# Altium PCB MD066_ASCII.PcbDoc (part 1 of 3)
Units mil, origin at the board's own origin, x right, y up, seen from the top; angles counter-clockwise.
Board outline 4255 x 2850 mil, 4 copper layers (Top Layer, Ground, Power, Bottom Layer), stack 61.6 mil thick; 158 components, 78 nets, 405 pads, 639 vias.
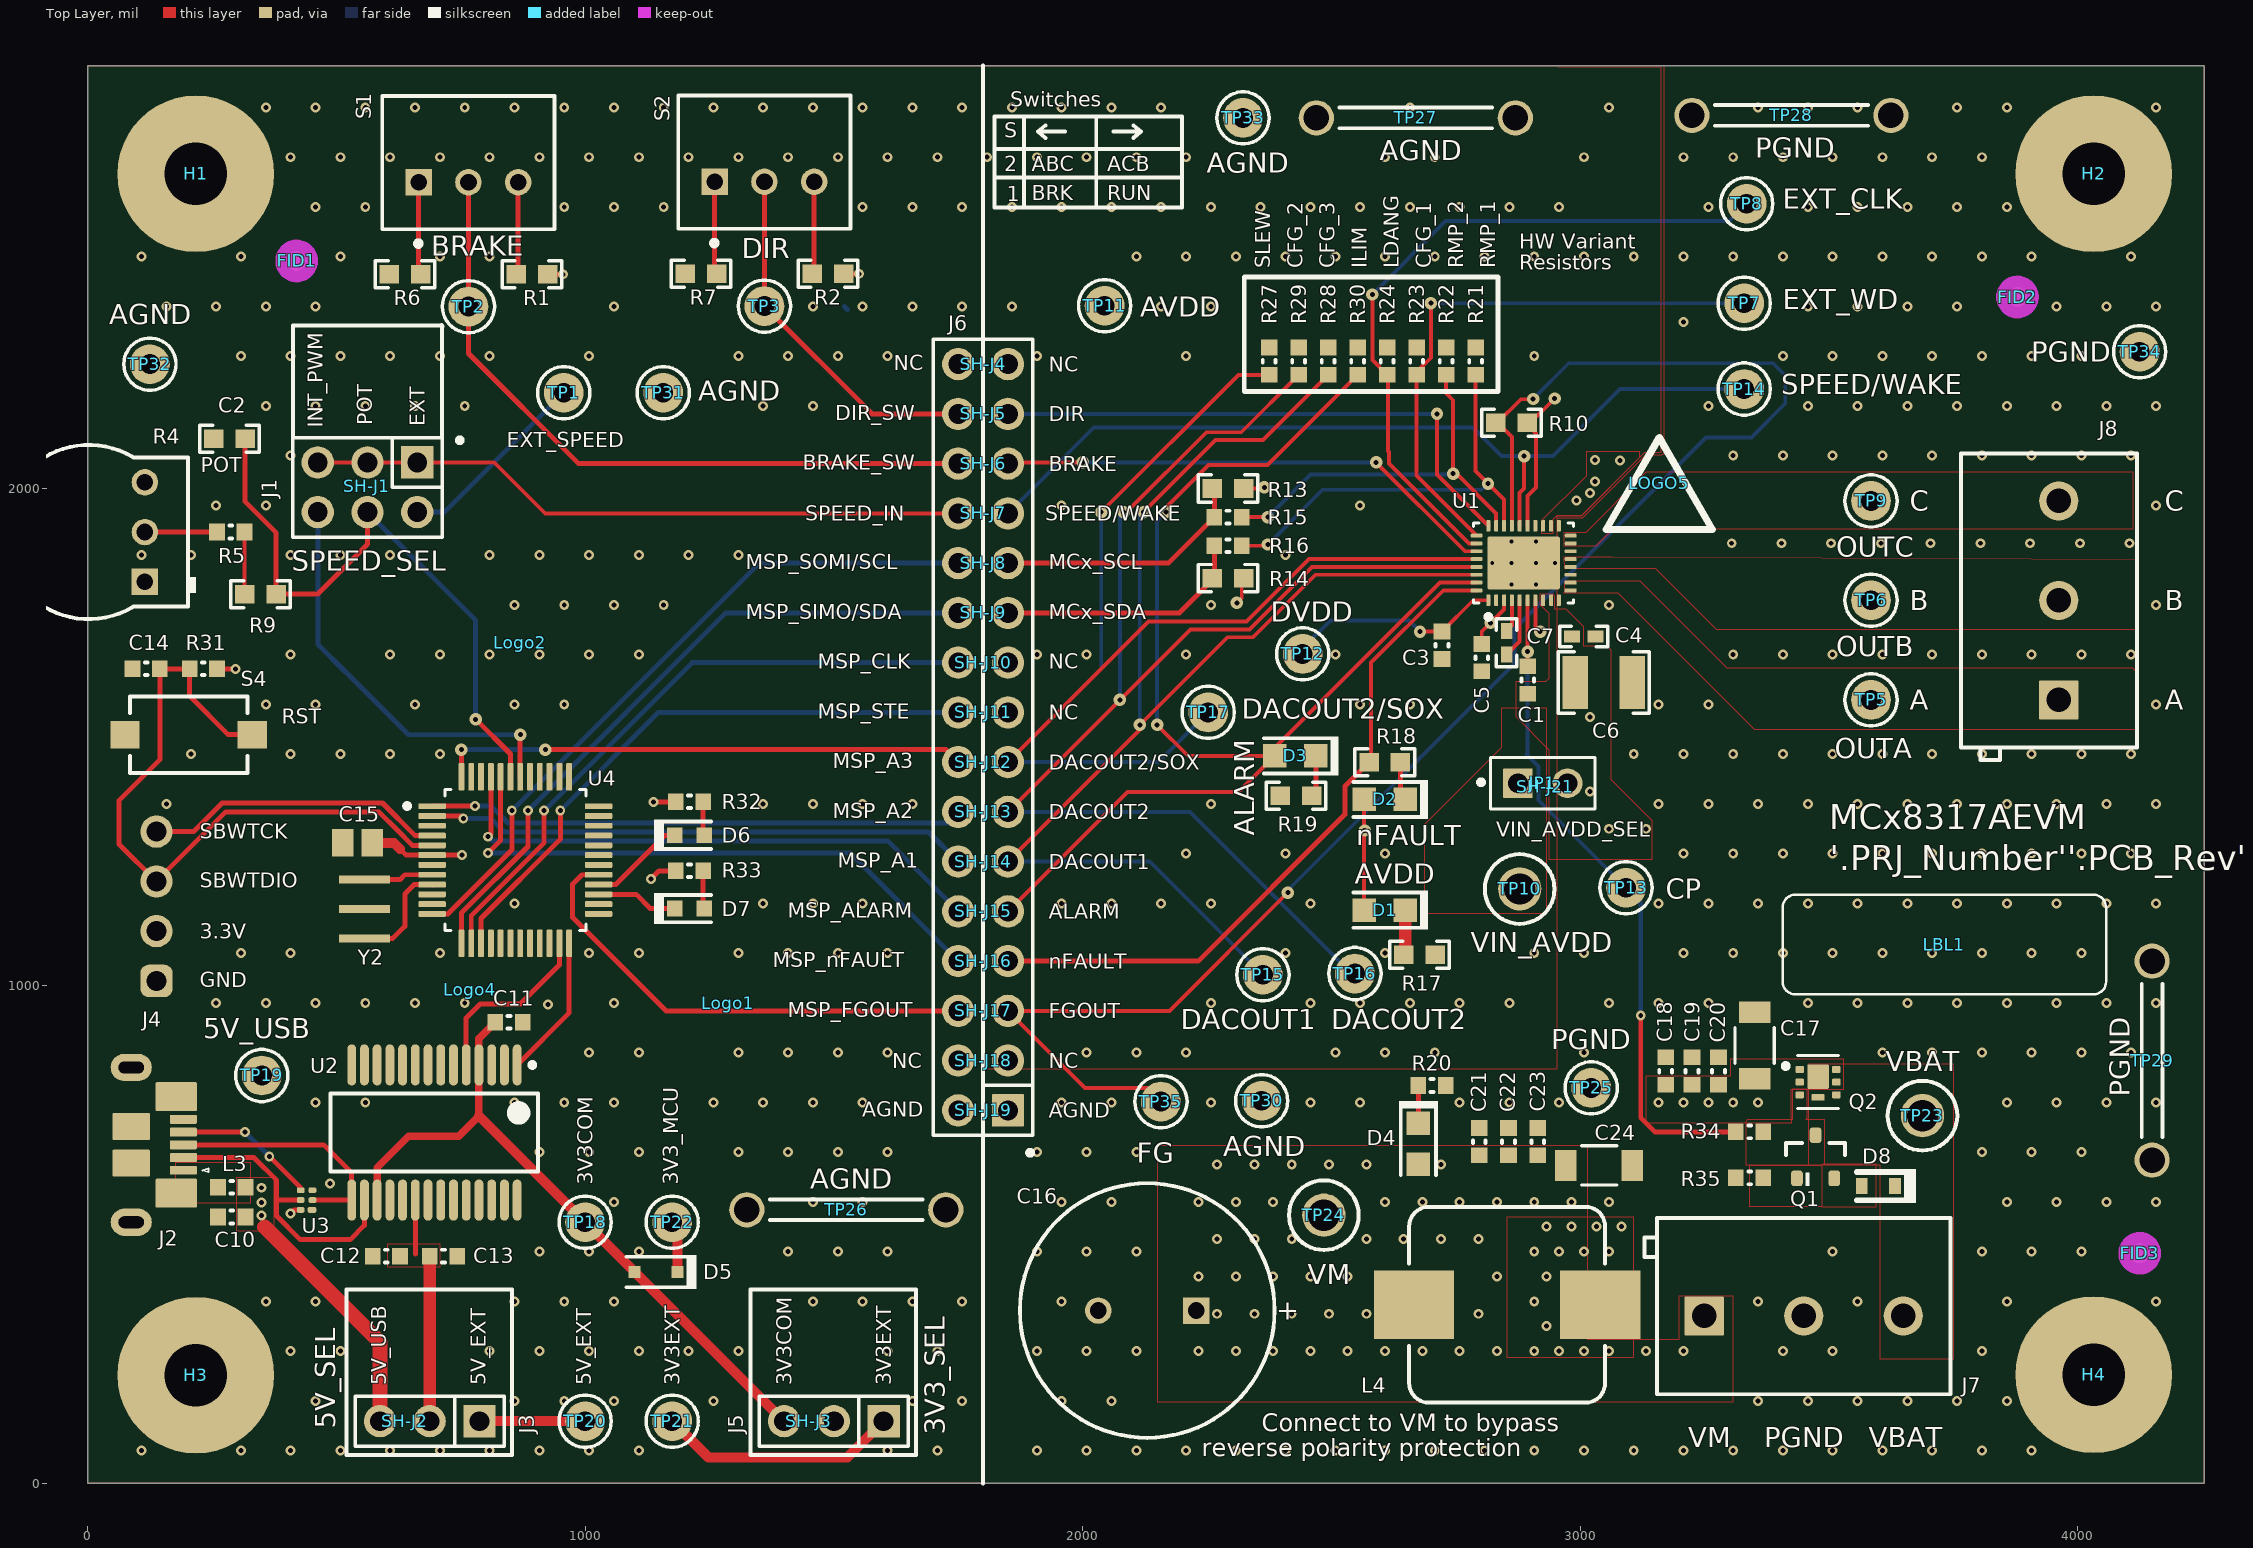
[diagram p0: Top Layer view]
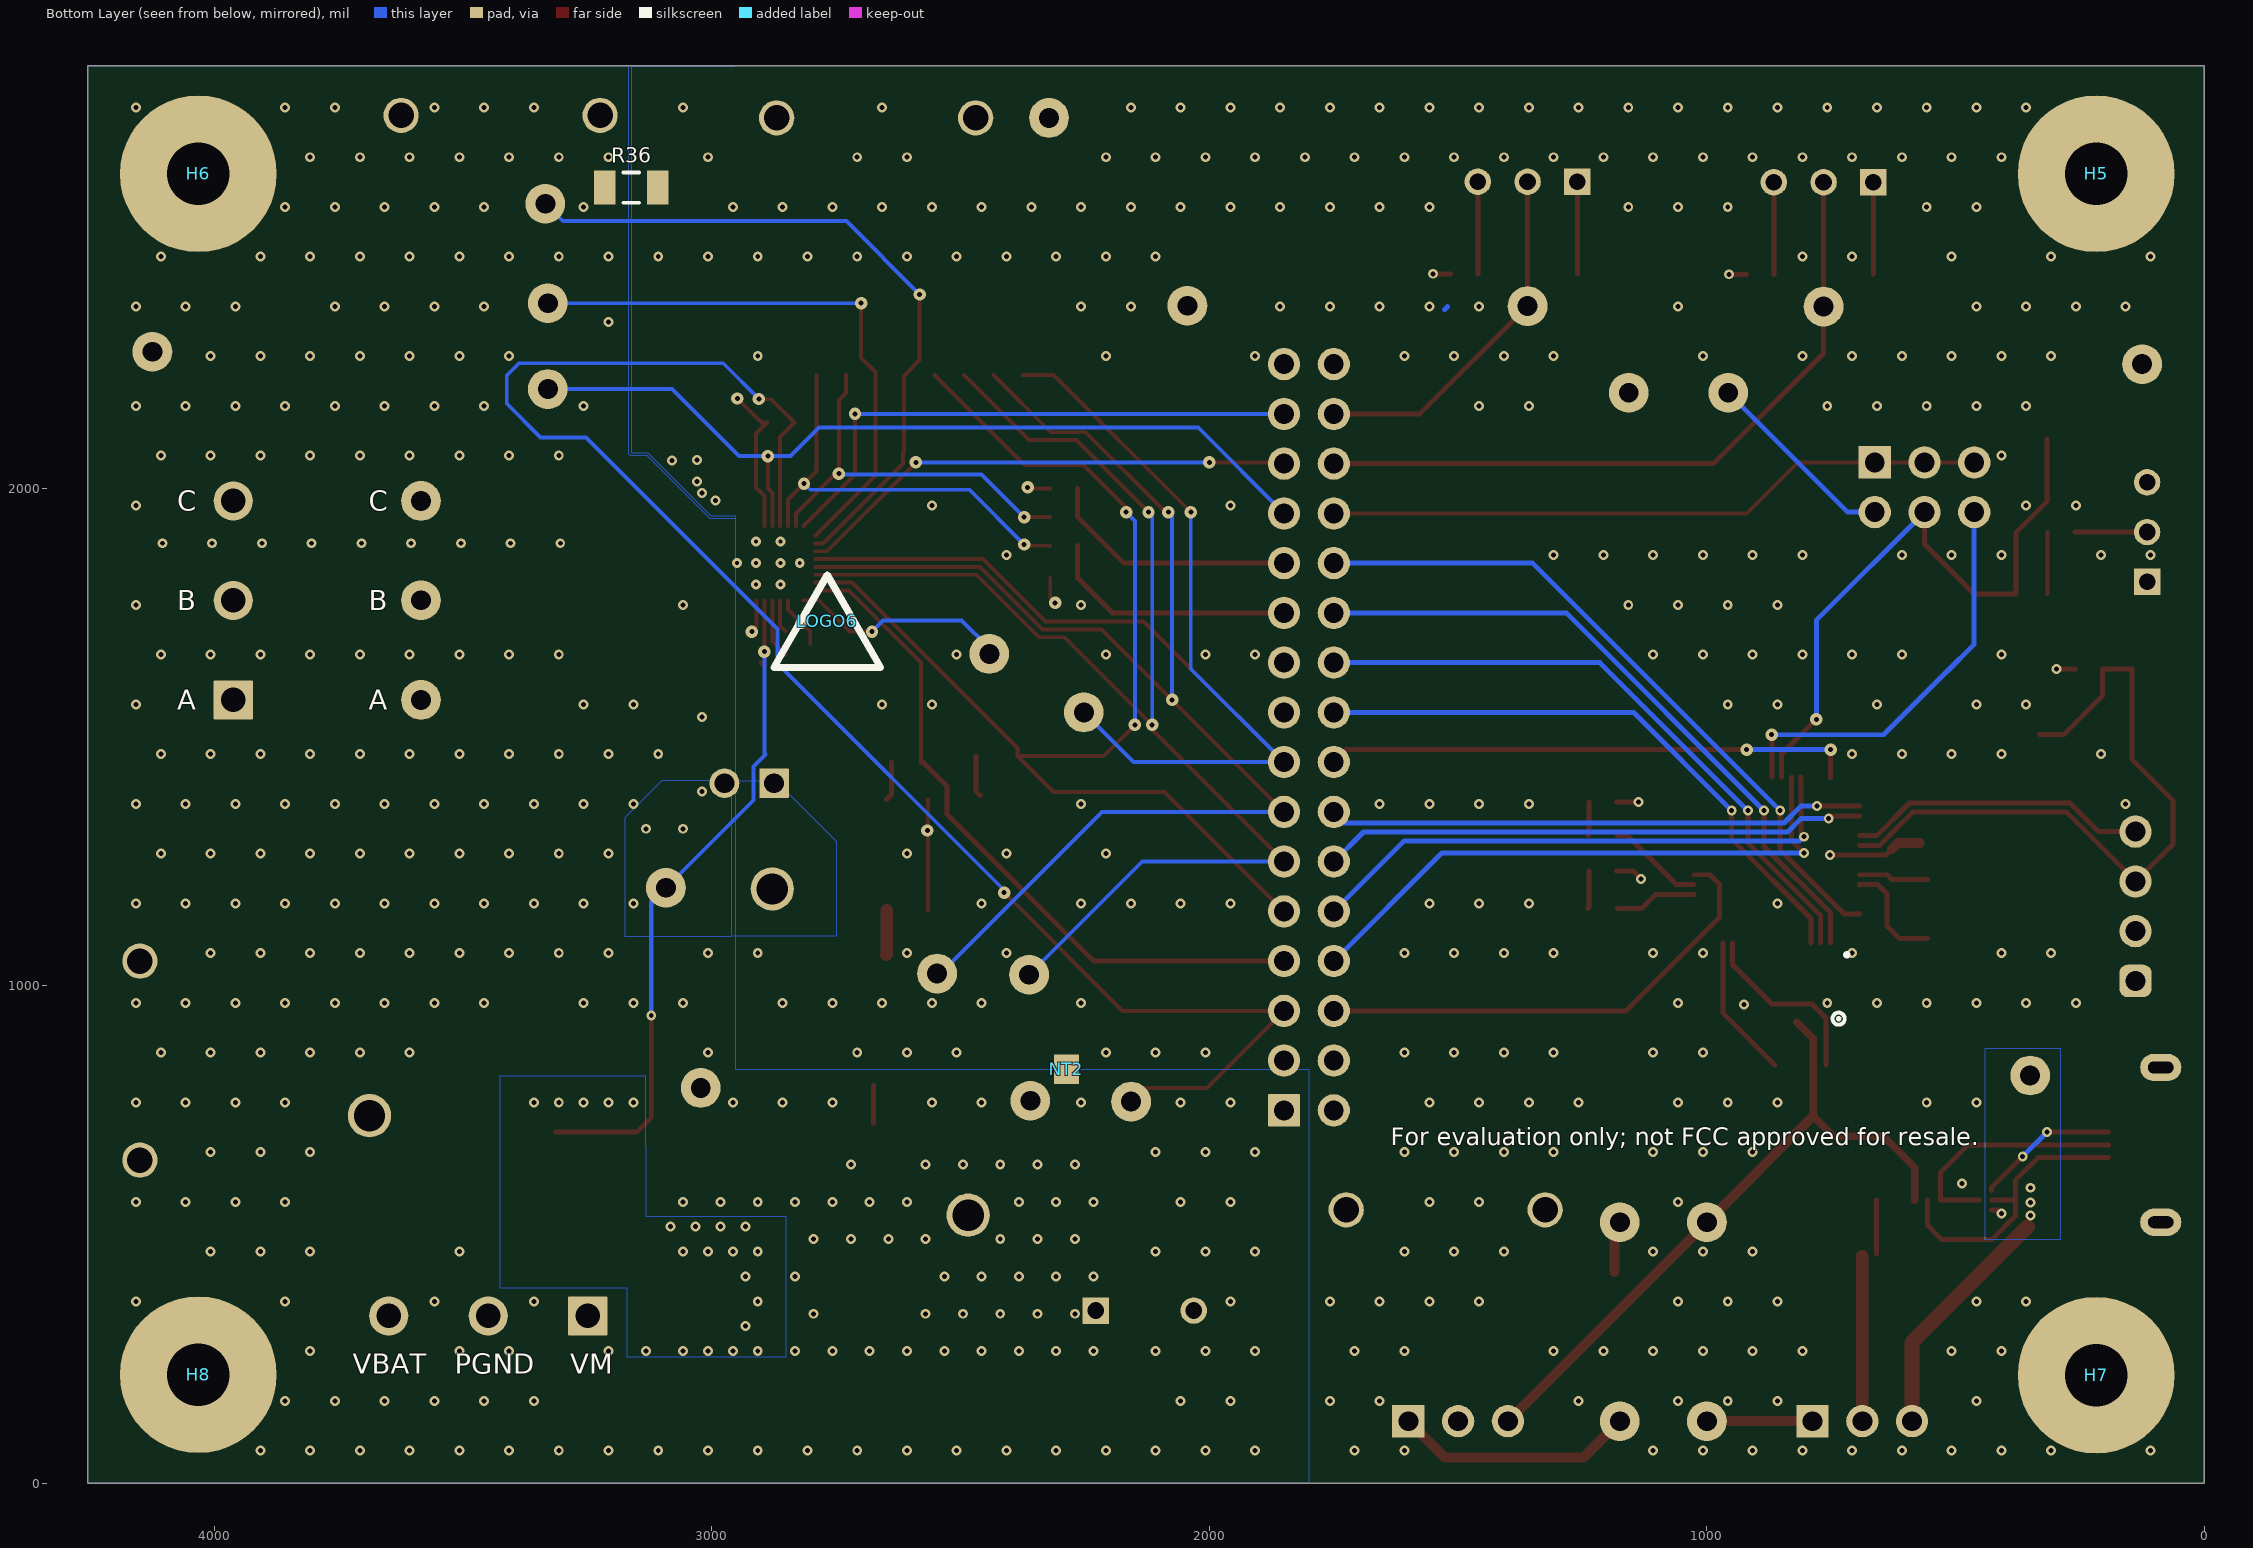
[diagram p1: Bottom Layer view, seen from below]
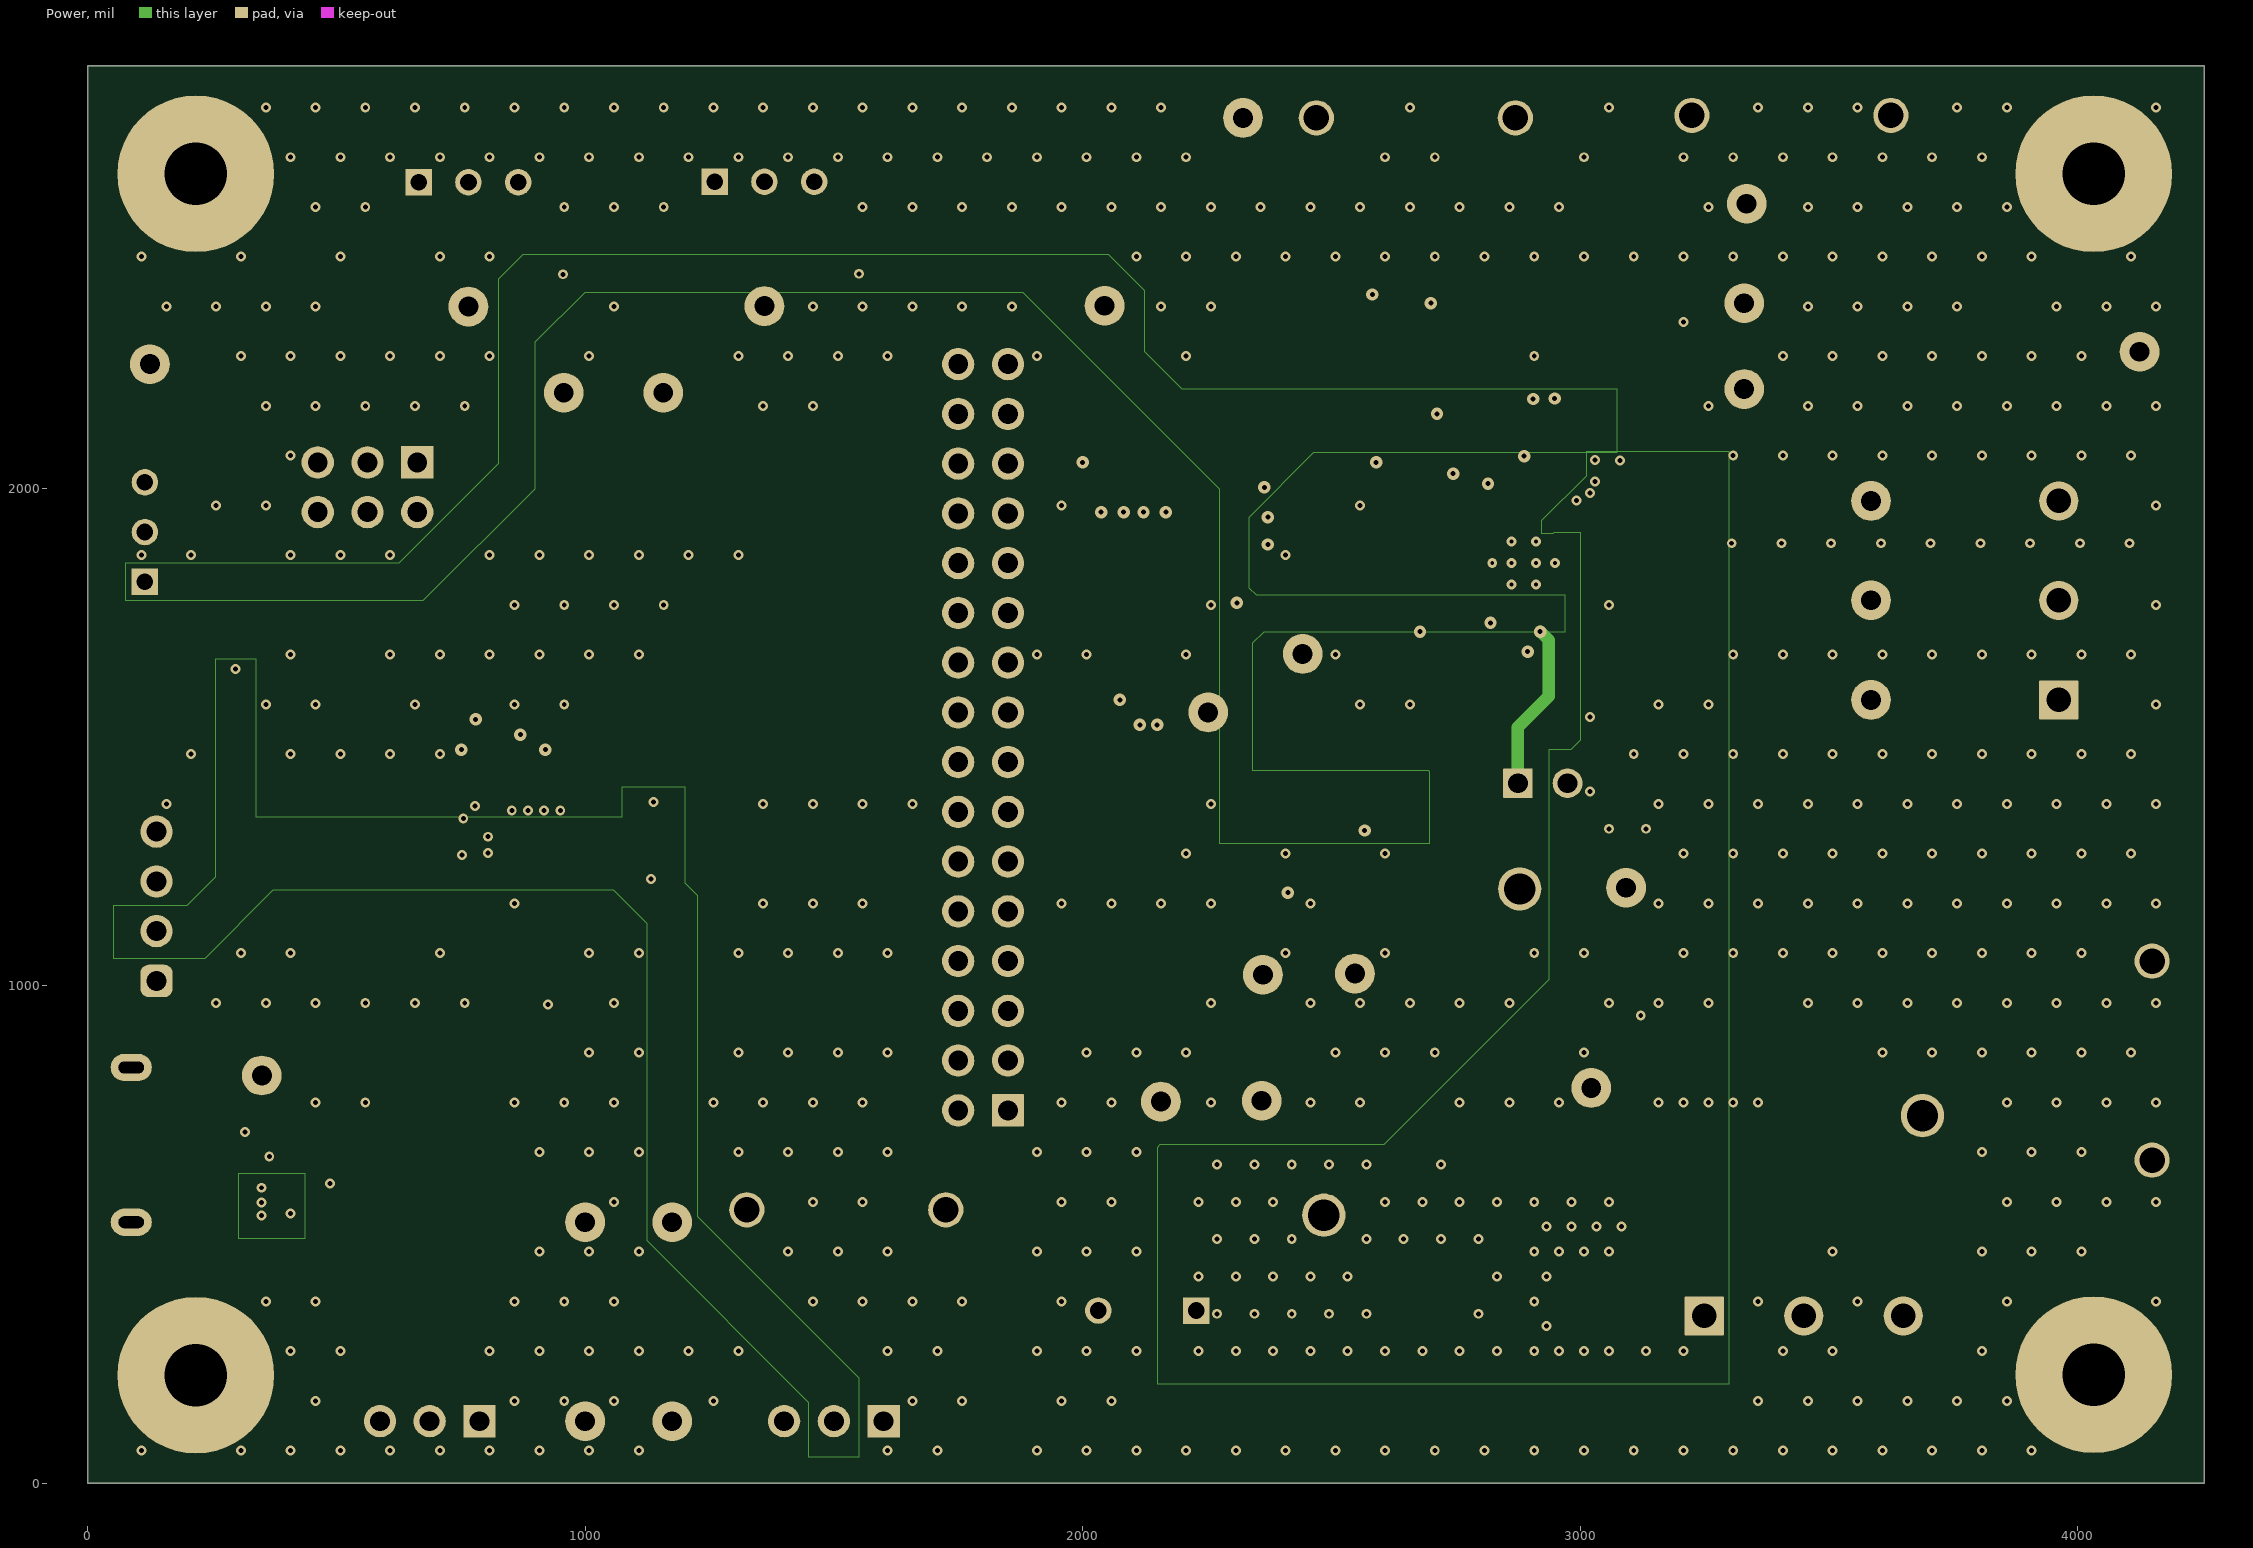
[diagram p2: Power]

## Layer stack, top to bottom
Top Solder: solder mask 0.4, Solder Resist, Dk 3.5
Top Layer: signal copper 1.4
Dielectric 1: prepreg 8, FR-4, Dk 4.2
Ground: signal copper 1.4
Dielectric 2: core 40, FR-4, Dk 4.2
Power: signal copper 1.4
Dielectric 3: prepreg 8, FR-4, Dk 4.2
Bottom Layer: signal copper 1.4
Bottom Solder: solder mask 0.4, Solder Resist, Dk 3.5

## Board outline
0,0 0,2850 4255,2850 4255,0

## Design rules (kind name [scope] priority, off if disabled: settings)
AcuteAngle [All] p0: scope1count=1 scope1_0_kind=Board scope1_0_value=Board scope2count=1 scope2_0_kind=Board scope2_0_value=Board commentlength=0 minimum=4.50000000000000E+0001
AcuteAngle [All] p1: minimum=4.50000000000000E+0001 checktracksonly=FALSE
AssemblyTestPointUsage [All] p0: scope1count=1 scope1_0_kind=Board scope1_0_value=Board scope2count=1 scope2_0_kind=Board scope2_0_value=Board commentlength=0
AssemblyTestPointUsage [All] p1: valid=2
AssemblyTestpoint [All] p0: scope1count=1 scope1_0_kind=Board scope1_0_value=Board scope2count=1 scope2_0_kind=Board scope2_0_value=Board commentlength=0
BoardOutlineClearance [All] p0 off: scope1count=1 scope1_0_kind=Board scope1_0_value=Board scope2count=1 scope2_0_kind=Board scope2_0_value=Board commentlength=172 gap=30 // Protel DXP Scope 1 Expression Was: OnCopper and Not InComponentClass('Logo') and not InComponentClass('FiducialMark') and not InRegion(1000,500,4000,800) and not InPoly
BoardOutlineClearance BoardOutlineClearance_Poly [All] p0 off: scope1count=1 scope1_0_kind=Board scope1_0_value=Board scope2count=1 scope2_0_kind=Board scope2_0_value=Board commentlength=58 gap=25 // Protel DXP Scope 1 Expression Was: OnCopper and IsPoly
BoardOutlineClearance BoardOutlineClearance_MountingHoles [All] p0 off: scope1count=1 scope1_0_kind=Board scope1_0_value=Board scope2count=1 scope2_0_kind=Board scope2_0_value=Board commentlength=86 gap=39.37 // Protel DXP Scope 1 Expression Was: OnCopper and InComponentClass('Mounting Holes')
BoardOutlineClearance BoardOutlineClearance_MountingHoles [OnCopper and InComponentClass('Mounting Holes')] p1: gap=39.37 ignorepadtopadclearanceinfootprint=FALSE
BoardOutlineClearance BoardOutlineClearance_Poly [OnCopper and IsPoly] p2: gap=25 ignorepadtopadclearanceinfootprint=FALSE
BoardOutlineClearance [OnCopper and Not InComponentClass('Logo') and not InComponentClass('FiducialMark') and not InRegion(1000,500,4000,800) and not InPoly] p3: gap=30 ignorepadtopadclearanceinfootprint=FALSE
Clearance "Stitching AGND" [All] p0 off: scope1count=1 scope1_0_kind=Board scope1_0_value=Board scope2count=1 scope2_0_kind=Board scope2_0_value=Board commentlength=80 gap=70 // Protel DXP Scope 2 Expression Was: (IsVia and (Not IsStitchingVia)) Or IsPad
Clearance [All] p0: scope1count=1 scope1_0_kind=Board scope1_0_value=Board scope2count=1 scope2_0_kind=Board scope2_0_value=Board commentlength=0 gap=7.87
Clearance Clearance_FiducialMark [All] p0 off: scope1count=1 scope1_0_kind=Board scope1_0_value=Board scope2count=1 scope2_0_kind=Board scope2_0_value=Board commentlength=81 gap=0 // Protel DXP Scope 2 Expression Was: IsPad and InComponentClass('FiducialMark')
Clearance Clearance_Poly [All] p0 off: scope1count=1 scope1_0_kind=Board scope1_0_value=Board scope2count=1 scope2_0_kind=Board scope2_0_value=Board commentlength=48 gap=7.87 // Protel DXP Scope 1 Expression Was: InPolygon
Clearance Clearance_Keepouts [All] p0 off: scope1count=1 scope1_0_kind=Board scope1_0_value=Board scope2count=1 scope2_0_kind=Board scope2_0_value=Board commentlength=99 gap=0 // Protel DXP Scope 2 Expression Was: ((IsTrack Or IsArc) And Not InPoly) And IsFree and IsKeepOut
Clearance "Stitching AGND" [IsStitchingVia and InNet('AGND') vs (IsVia and (Not IsStitchingVia)) Or IsPad] p1: gap=70 ignorepadtopadclearanceinfootprint=TRUE
Clearance Clearance_Keepouts [((IsTrack Or IsArc) And Not InPoly) And IsFree and IsKeepOut vs ((IsTrack Or IsArc) And Not InPoly) And IsFree and IsKeepOut] p2: gap=0 ignorepadtopadclearanceinfootprint=FALSE
Clearance Clearance_Poly [InPolygon] p3: gap=7.87 ignorepadtopadclearanceinfootprint=TRUE except(5: Arc-Fill Arc-Poly Arc-Region Track-Fill Track-Poly Track-Region SMDPad-Fill SMDPad-Poly SMDPad-Region THPad-Fill THPad-Poly THPad-Region Via-Fill Via-Poly Via-Region Fill-Fill Fill-Poly Fill-Region Poly-Poly Poly-Region Region-Region)
Clearance Clearance_FiducialMark [IsKeepOut and InComponentClass('FiducialMark') vs IsPad and InComponentClass('FiducialMark')] p4: gap=0 ignorepadtopadclearanceinfootprint=FALSE
Clearance [All] p5: gap=7.87 ignorepadtopadclearanceinfootprint=TRUE
ComponentClearance [All] p0: scope1count=1 scope1_0_kind=Board scope1_0_value=Board scope2count=1 scope2_0_kind=Board scope2_0_value=Board commentlength=0 gap=0 collisioncheckmode=3
ComponentClearance ComponentClearance_THtoTH [All] p0 off: scope1count=1 scope1_0_kind=Board scope1_0_value=Board scope2count=1 scope2_0_kind=Board scope2_0_value=Board commentlength=54 gap=0 collisioncheckmode=3 // Protel DXP Scope 2 Expression Was: IsThruComponent
ComponentClearance ComponentClearance_THtoSMT [All] p0 off: scope1count=1 scope1_0_kind=Board scope1_0_value=Board scope2count=1 scope2_0_kind=Board scope2_0_value=Board commentlength=53 gap=0 collisioncheckmode=3 // Protel DXP Scope 2 Expression Was: IsSMTComponent
ComponentClearance ComponentClearance_SmallPassives [All] p0 off: scope1count=1 scope1_0_kind=Board scope1_0_value=Board scope2count=1 scope2_0_kind=Board scope2_0_value=Board commentlength=508 gap=14.96 collisioncheckmode=3 // Protel DXP Scope 2 Expression Was: HasFootprint('0201*') or HasFootprint('0402*') or HasFootprint('0508') or HasFootprint('0603*') or HasFootprint('0612') or HasFootprint('0805*') or HasFootprint('0815*') or HasFootprint('0830*') or HasFootprint('1206*') or HasFootprint('1210*') or HasFootprint('1808*') or HasFootprint('1812*') or HasFootprint('1825*') or HasFootprint('2010*') or HasFootprint('2220*') or HasFootprint('2225*') or HasFootprint('2512*') or HasFootprint('2728*') or HasFootprint('3518*')
ComponentClearance ComponentClearance_MountingHoles [All] p0: scope1count=1 scope1_0_kind=ComponentClass scope1_0_value="Mounting Holes" scope2count=1 scope2_0_kind=Board scope2_0_value=Board commentlength=0 gap=150 collisioncheckmode=3
ComponentClearance ComponentClearance_ScrewToNut [All] p0 off: scope1count=1 scope1_0_kind=Board scope1_0_value=Board scope2count=1 scope2_0_kind=Board scope2_0_value=Board commentlength=71 gap=5 collisioncheckmode=3 // Protel DXP Scope 2 Expression Was: (HasFootprint('Keystone_1902C'))
ComponentClearance ComponentClearance_Logo [All] p0: scope1count=1 scope1_0_kind=ComponentClass scope1_0_value=Logo scope2count=1 scope2_0_kind=Board scope2_0_value=Board commentlength=0 gap=50 collisioncheckmode=3
ComponentClearance ComponentClearance_Shunt [All] p0: scope1count=1 scope1_0_kind=ComponentClass scope1_0_value=Header scope2count=1 scope2_0_kind=ComponentClass scope2_0_value=Shunt commentlength=0 gap=0 collisioncheckmode=3
ComponentClearance ComponentClearance_MountingHoles_FiducialMarks [All] p0: scope1count=1 scope1_0_kind=ComponentClass scope1_0_value="Mounting Holes" scope2count=1 scope2_0_kind=ComponentClass scope2_0_value=FiducialMark commentlength=0 gap=50 collisioncheckmode=3
ComponentClearance ComponentClearance_MountingHoles_FiducialMarks [InComponentClass('Mounting Holes') vs InComponentClass('FiducialMark')] p1: gap=50 collisioncheckmode=3 verticalgap=10 showdistances=FALSE
ComponentClearance ComponentClearance_Shunt [InComponentClass('Header') vs InComponentClass('Shunt')] p2: gap=0 collisioncheckmode=3 verticalgap=0 showdistances=FALSE
ComponentClearance ComponentClearance_Logo [InComponentClass('Logo')] p3: gap=50 collisioncheckmode=3 verticalgap=10 showdistances=FALSE
ComponentClearance ComponentClearance_ScrewToNut [(HasFootprint('NY PMS 440 0025 PH')) vs (HasFootprint('Keystone_1902C'))] p4: gap=5 collisioncheckmode=3 verticalgap=10 showdistances=FALSE
ComponentClearance ComponentClearance_MountingHoles [InComponentClass('Mounting Holes')] p5: gap=150 collisioncheckmode=3 verticalgap=100000 showdistances=FALSE
ComponentClearance ComponentClearance_SmallPassives [HasFootprint('0201*') or HasFootprint('0402*') or HasFootprint('0508') or HasFootprint('0603*') or HasFootprint('0612') or HasFootprint('0805*') or HasFootprint('0815*') or HasFootprint('0830*') or HasFootprint('1206*') or HasFootprint('1210*') or HasFootprint('1808*') or HasFootprint('1812*') or HasFootprint('1825*') or HasFootprint('2010*') or HasFootprint('2220*') or HasFootprint('2225*') or HasFootprint('2512*') or HasFootprint('2728*') or HasFootprint('3518*') vs HasFootprint('0201*') or HasFootprint('0402*') or HasFootprint('0508') or HasFootprint('0603*') or HasFootprint('0612') or HasFootprint('0805*') or HasFootprint('0815*') or HasFootprint('0830*') or HasFootprint('1206*') or HasFootprint('1210*') or HasFootprint('1808*') or HasFootprint('1812*') or HasFootprint('1825*') or HasFootprint('2010*') or HasFootprint('2220*') or HasFootprint('2225*') or HasFootprint('2512*') or HasFootprint('2728*') or HasFootprint('3518*')] p6: gap=14.96 collisioncheckmode=3 verticalgap=10 showdistances=FALSE
ComponentClearance ComponentClearance_THtoSMT [IsThruComponent vs IsSMTComponent] p7: gap=0 collisioncheckmode=3 verticalgap=0 showdistances=FALSE
ComponentClearance ComponentClearance_THtoTH [IsThruComponent vs IsThruComponent] p8: gap=0 collisioncheckmode=3 verticalgap=0 showdistances=FALSE
ComponentClearance [All] p9: gap=0 collisioncheckmode=3 verticalgap=0 showdistances=FALSE
DiffPairsRouting [All] p0: scope1count=1 scope1_0_kind=Board scope1_0_value=Board scope2count=1 scope2_0_kind=Board scope2_0_value=Board commentlength=0
DiffPairsRouting [All] p1: maxlimit=100 minlimit=10 mostfreqgap=10 toplayer_minwidth=15 toplayer_maxwidth=15 toplayer_prefwidth=15 midlayer1_minwidth=15 midlayer1_maxwidth=15 midlayer1_prefwidth=15 midlayer2_minwidth=15 midlayer2_maxwidth=15 midlayer2_prefwidth=15 bottomlayer_minwidth=15 bottomlayer_maxwidth=15 bottomlayer_prefwidth=15 maxuncoupledlength=1000
FabricationTestPointUsage TestPointUsage [All] p0: scope1count=1 scope1_0_kind=Board scope1_0_value=Board scope2count=1 scope2_0_kind=Board scope2_0_value=Board commentlength=0 valid=2 allowmultiple=FALSE
FabricationTestPointUsage TestPointUsage [All] p1: valid=2 allowmultiple=FALSE
FabricationTestpoint Testpoint [All] p0: scope1count=1 scope1_0_kind=Board scope1_0_value=Board scope2count=1 scope2_0_kind=Board scope2_0_value=Board commentlength=0 side=3 testpointundercomponent=TRUE minsize=40 maxsize=100 preferedsize=60 minholesize=0 maxholesize=40 preferedholesize=32 testpointgrid=1
FabricationTestpoint Testpoint [All] p1: side=3 testpointundercomponent=TRUE minsize=40 maxsize=100 preferedsize=60 minholesize=0 maxholesize=40 preferedholesize=32 testpointgrid=1 allowsidetop=TRUE allowsidebottom=TRUE usegrid=TRUE gridtolerance=0.01
FanoutControl Fanout_Small [All] p0 off: scope1count=1 scope1_0_kind=Board scope1_0_value=Board scope2count=1 scope2_0_kind=Board scope2_0_value=Board commentlength=84 // Protel DXP Scope 1 Expression Was: (CompPinCount < 5)   Fanout_Small (Default Rule)
FanoutControl Fanout_Default [All] p0: scope1count=1 scope1_0_kind=Board scope1_0_value=Board scope2count=1 scope2_0_kind=Board scope2_0_value=Board commentlength=30 // Fanout_Default (Default Rule)
FanoutControl Fanout_SOIC [All] p0 off: scope1count=1 scope1_0_kind=Board scope1_0_value=Board scope2count=1 scope2_0_kind=Board scope2_0_value=Board commentlength=71 // Protel DXP Scope 1 Expression Was: IsSOIC   Fanout_SOIC (Default Rule)
FanoutControl Fanout_BGA [All] p0 off: scope1count=1 scope1_0_kind=Board scope1_0_value=Board scope2count=1 scope2_0_kind=Board scope2_0_value=Board commentlength=69 // Protel DXP Scope 1 Expression Was: IsBGA   Fanout_BGA (Default Rule)
FanoutControl Fanout_LCC [All] p0 off: scope1count=1 scope1_0_kind=Board scope1_0_value=Board scope2count=1 scope2_0_kind=Board scope2_0_value=Board commentlength=69 // Protel DXP Scope 1 Expression Was: IsLCC   Fanout_LCC (Default Rule)
FanoutControl Fanout_LCC [IsLCC] p1: bgadir=Out bgaviamode=Centered fanoutstyle=Auto fanoutdirection=Alternating viagrid=1 // Fanout_LCC (Default Rule)
FanoutControl Fanout_BGA [IsBGA] p2: bgadir=Out bgaviamode=Centered fanoutstyle=Auto fanoutdirection=Alternating viagrid=1 // Fanout_BGA (Default Rule)
FanoutControl Fanout_Default [All] p4: bgadir=Out bgaviamode=Centered fanoutstyle=Auto fanoutdirection=Alternating viagrid=1 // Fanout_Default (Default Rule)
FanoutControl Fanout_Small [(CompPinCount < 5)] p5: bgadir=Out bgaviamode=Centered fanoutstyle=Auto fanoutdirection=OutThenIn viagrid=1 // Fanout_Small (Default Rule)
Height [All] p0: scope1count=1 scope1_0_kind=Board scope1_0_value=Board scope2count=1 scope2_0_kind=Board scope2_0_value=Board commentlength=0
HoleSize [All] p0: scope1count=1 scope1_0_kind=Board scope1_0_value=Board scope2count=1 scope2_0_kind=Board scope2_0_value=Board commentlength=0 absolutevalues=TRUE maxlimit=200 minlimit=1 maxpercent=80.000 minpercent=20.000
HoleSize [All] p1: absolutevalues=TRUE maxlimit=200 minlimit=1 maxpercent=80.000 minpercent=20.000
HoleToHoleClearance [All] p0: scope1count=1 scope1_0_kind=Board scope1_0_value=Board scope2count=1 scope2_0_kind=Board scope2_0_value=Board commentlength=0
LayerPairs [All] p0: scope1count=1 scope1_0_kind=Board scope1_0_value=Board scope2count=1 scope2_0_kind=Board scope2_0_value=Board commentlength=0 enforce=TRUE
MinimumAnnularRing [All] p0: scope1count=1 scope1_0_kind=Board scope1_0_value=Board scope2count=1 scope2_0_kind=Board scope2_0_value=Board commentlength=0 minimumring=1
MinimumAnnularRing MinimumAnnularRing_ThermalPadVias [All] p0 off: scope1count=1 scope1_0_kind=Board scope1_0_value=Board scope2count=1 scope2_0_kind=Board scope2_0_value=Board commentlength=63 minimumring=1 // Protel DXP Scope 1 Expression Was: IsVia and InAnyComponent
MinimumAnnularRing MinimumAnnularRing_ThermalPadVias [IsVia and InAnyComponent] p1: minimumring=1
MinimumAnnularRing [All] p2: minimumring=1
MinimumSolderMaskSliver [All] p0: scope1count=1 scope1_0_kind=Board scope1_0_value=Board scope2count=1 scope2_0_kind=Board scope2_0_value=Board commentlength=0
MinimumSolderMaskSliver MinimumSolderMaskSliver_Logo [All] p0: scope1count=1 scope1_0_kind=ComponentClass scope1_0_value=Logo scope2count=1 scope2_0_kind=ComponentClass scope2_0_value=Logo commentlength=0
MinimumSolderMaskSliver MinimumSolderMaskSliver_Logo [InComponentClass('Logo') vs InComponentClass('Logo')] p1: minsoldermaskwidth=0.7
MinimumSolderMaskSliver [All] p2: minsoldermaskwidth=1
NetAntennae [All] p0: scope1count=1 scope1_0_kind=Board scope1_0_value=Board scope2count=1 scope2_0_kind=Board scope2_0_value=Board commentlength=0
PasteMaskExpansion [All] p0: scope1count=1 scope1_0_kind=Board scope1_0_value=Board scope2count=1 scope2_0_kind=Board scope2_0_value=Board commentlength=0 expansion=0
PlaneClearance [All] p0: scope1count=1 scope1_0_kind=Board scope1_0_value=Board scope2count=1 scope2_0_kind=Board scope2_0_value=Board commentlength=0 clearance=20
PlaneConnect [All] p0: scope1count=1 scope1_0_kind=Board scope1_0_value=Board scope2count=1 scope2_0_kind=Board scope2_0_value=Board commentlength=0 planeconnectstyle=Relief reliefexpansion=10 reliefentries=4 reliefconductorwidth=10 reliefairgap=10
PlaneConnect [All] p1: planeconnectstyle=Relief reliefexpansion=10 reliefentries=4 reliefconductorwidth=10 reliefairgap=10
PolygonConnect [All] p0: scope1count=1 scope1_0_kind=Board scope1_0_value=Board scope2count=1 scope2_0_kind=Board scope2_0_value=Board commentlength=0 connectstyle=Direct reliefconductorwidth=10 reliefentries=4 polygonreliefangle="90 Angle"
PolygonConnect [All] p1: connectstyle=Direct reliefconductorwidth=10 reliefentries=4 polygonreliefangle="90 Angle" airgapwidth=10
RoutingCorners [All] p0: scope1count=1 scope1_0_kind=Board scope1_0_value=Board scope2count=1 scope2_0_kind=Board scope2_0_value=Board commentlength=0 cornerstyle=45-Degree minsetback=100 maxsetback=100
RoutingLayers [All] p0: scope1count=1 scope1_0_kind=Board scope1_0_value=Board scope2count=1 scope2_0_kind=Board scope2_0_value=Board commentlength=0 top layer=Automatic mid layer 1=Automatic mid layer 2=Automatic bottom layer=Automatic
RoutingPriority [All] p0: scope1count=1 scope1_0_kind=Board scope1_0_value=Board scope2count=1 scope2_0_kind=Board scope2_0_value=Board commentlength=0
RoutingTopology [All] p0: scope1count=1 scope1_0_kind=Board scope1_0_value=Board scope2count=1 scope2_0_kind=Board scope2_0_value=Board commentlength=0 topology=Shortest
RoutingVias [All] p0: scope1count=1 scope1_0_kind=Board scope1_0_value=Board scope2count=1 scope2_0_kind=Board scope2_0_value=Board commentlength=0 holewidth=10 width=25 viastyle="Through Hole" minholewidth=7 minwidth=20 maxholewidth=15 maxwidth=30
RoutingVias ThermalPadVias [All] p0 off: scope1count=1 scope1_0_kind=Board scope1_0_value=Board scope2count=1 scope2_0_kind=Board scope2_0_value=Board commentlength=63 holewidth=7.87 width=19.68 viastyle="Through Hole" minholewidth=7.87 minwidth=19.68 maxholewidth=12.99 maxwidth=23.62 // Protel DXP Scope 1 Expression Was: IsVia and InAnyComponent
RoutingVias ThermalPadVias [IsVia and InAnyComponent] p1: holewidth=7.87 width=19.68 viastyle="Through Hole" minholewidth=7.87 minwidth=19.68 maxholewidth=12.99 maxwidth=23.62
RoutingVias [All] p2: holewidth=10 width=25 viastyle="Through Hole" minholewidth=7 minwidth=20 maxholewidth=15 maxwidth=30
ShortCircuit [All] p0: scope1count=1 scope1_0_kind=Board scope1_0_value=Board scope2count=1 scope2_0_kind=Board scope2_0_value=Board commentlength=0 allowed=FALSE
SilkToBoardRegionClearance [All] p0 off: scope1count=1 scope1_0_kind=Board scope1_0_value=Board scope2count=1 scope2_0_kind=Board scope2_0_value=Board commentlength=130 // Protel DXP Scope 1 Expression Was: Not ((IsComment or IsDesignator) And (Hide <> 'False')) and not InRegion(1000,500,4000,800)
SilkToBoardRegionClearance [Not ((IsComment or IsDesignator) And (Hide <> 'False')) and not InRegion(1000,500,4000,800)] p1:
SilkToSilkClearance [All] p0: scope1count=1 scope1_0_kind=Board scope1_0_value=Board scope2count=1 scope2_0_kind=Board scope2_0_value=Board commentlength=0
SilkToSilkClearance SilkToSilkClearance_Pb-FreeLogo [All] p0 off: scope1count=1 scope1_0_kind=Board scope1_0_value=Board scope2count=1 scope2_0_kind=Board scope2_0_value=Board commentlength=120 // Protel DXP Scope 2 Expression Was: (HasFootprint('Pb-Free_Overlay_Medium') OR HasFootprint('Pb-Free_Overlay_Small'))
SilkToSilkClearance SilkToSilkClearance_Pb-FreeLogo [(HasFootprint('Pb-Free_Overlay_Medium') OR HasFootprint('Pb-Free_Overlay_Small')) vs (HasFootprint('Pb-Free_Overlay_Medium') OR HasFootprint('Pb-Free_Overlay_Small'))] p1: silktosilkclearance=1
SilkToSilkClearance [All] p2: silktosilkclearance=1
SilkToSolderMaskClearance [All] p0 off: scope1count=1 scope1_0_kind=Board scope1_0_value=Board scope2count=1 scope2_0_kind=Board scope2_0_value=Board commentlength=44 // Protel DXP Scope 1 Expression Was: IsPad
SilkToSolderMaskClearance [IsPad] p1: minsilkscreentomaskgap=1 clearancetoexposedcopper=TRUE
SolderMaskExpansion [All] p0: scope1count=1 scope1_0_kind=Board scope1_0_value=Board scope2count=1 scope2_0_kind=Board scope2_0_value=Board commentlength=0 expansion=1.97
SolderMaskExpansion [All] p1: expansion=1.97
UnRoutedNet [All] p0: scope1count=1 scope1_0_kind=Board scope1_0_value=Board scope2count=1 scope2_0_kind=Board scope2_0_value=Board commentlength=0
UnRoutedNet [All] p1: checkbadconnections=TRUE
UnpouredPolygon [All] p0: scope1count=1 scope1_0_kind=Board scope1_0_value=Board scope2count=1 scope2_0_kind=Board scope2_0_value=Board commentlength=0
Width [All] p0: scope1count=1 scope1_0_kind=Board scope1_0_value=Board scope2count=1 scope2_0_kind=Board scope2_0_value=Board commentlength=0 maxlimit=100 minlimit=6 preferedwidth=10
Width [All] p1: maxlimit=100 minlimit=6 preferedwidth=10 checkconnectedcopper=TRUE
14 further rules are at their usual default settings.

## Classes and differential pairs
component class Label: LBL1
component class "Mounting Holes": H1 H2 H3 H4
component class MD066_INTERFACE: C10 C11 C12 C13 C14 C15 D5 D6 D7 J2 J3 J4 J5 J6 L3 R31 R32 R33 S4 SH-J2 SH-J3 SH-J4 SH-J5 SH-J6 SH-J7 SH-J8 SH-J9 SH-J10 SH-J11 SH-J12 SH-J13 SH-J14 SH-J15 SH-J16 SH-J17 SH-J18 SH-J19 TP18 TP19 TP20 TP21 TP22 U2 U3 U4 Y2
component class MD066_CONTROL: C2 J1 R1 R2 R4 R5 R6 R7 R9 S1 S2 SH-J1 TP1 TP2 TP3
component class Shunt: SH-J1 SH-J2 SH-J3 SH-J4 SH-J5 SH-J6 SH-J7 SH-J8 SH-J9 SH-J10 SH-J11 SH-J12 SH-J13 SH-J14 SH-J15 SH-J16 SH-J17 SH-J18 SH-J19 SH-J21
component class MD066_POWER_AND_CONNECTORS: AGND AGND1 C16 C17 C18 C19 C20 C21 C22 C23 C24 D8 J7 J8 J10 J11 JP1 L4 NT2 PGND PGND2 PGND3 Q1 Q2 R34 R35 R36 R45 SH-J21 TP10 TP23 TP24 TP25 TP26 TP27 TP28 TP29 TP30 TP31 TP32 TP33 TP34 TP_AGND1 TP_AGND2 TP_PGND vm VM1
component class MD066_DRIVER: 1 A1 B1 C1 C3 C4 C5 C6 C7 D1 D2 D3 D4 D? ILIM1 R10 R13 R14 R15 R16 R17 R18 R19 R20 R21 R22 R23 R24 R27 R28 R29 R30 TP5 TP6 TP7 TP8 TP9 TP11 TP12 TP13 TP14 TP15 TP16 TP17 TP35 U1
component class Header: J1 J3 J4 J5 J6 J10
component class Logo: Logo2
component class MD066_HARDWARE: FID1 FID2 FID3 H1 H2 H3 H4 H5 H6 H7 H8 LBL1 Logo1 Logo2 Logo3 Logo4 LOGO5 LOGO6 ZZ1 ZZ2 ZZ3 ZZ4
component class FiducialMark: FID1 FID2 FID3
component class AssemblyNote: ZZ1 ZZ2 ZZ3 ZZ4

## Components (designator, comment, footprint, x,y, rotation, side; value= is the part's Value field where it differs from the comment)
C1 "EMK107B7105KAHT" 0603L 2894.94,1615 r270 top
C2 "0603ZC101KAT2A" 0603 285,2100 r180 top
C3 "C0603C105K9RACAUTO" 0603L 2722.5,1685 r90 top
C4 "C1005X6S1H104K050BB" 0402 3007.5,1702.5 r0 top
C5 "C0603C105K9RACAUTO" 0603L 2802.5,1660 r90 top
C6 "GRM32ER71J106KA12L" 1210_270 3047.5,1610 r0 top
C7 "C1005X6S1H104K050BB" 0402 2852.5,1690 r90 top
C10 "0603ZC104KAT2A" 0603L 289.64,535.59 r180 top
C11 "0603ZC104KAT2A" 0603L 847.14,927.09 r0 top
C12 "GRM188Z71A475ME15D" 0603L 600.29,456.84 r0 top
C13 "0603ZC104KAT2A" 0603L 715.29,456.96 r0 top
C14 "885012206034" 0603L 117.5,1637.5 r180 top
C15 "885012207103" 0805L 542.5,1287.5 r180 top
C16 "ELXZ630ELL331MK20S" Chemi-Con_1250x2000 2130,347.5 r180 top
C17 "CL31B105KCHNNNE" 1206_180 3350.96,880.34 r90 top
C18 "CGA3E3X7S2A104K080AB" 0603L 3172.01,828.83 r90 top
C19 "CGA3E2X7R2A103K080AA" 0603L 3225.22,828.83 r90 top
C20 "CGA3E2X7R2A102K080AA" 0603L 3278.42,828.83 r90 top
C21 "CGA3E2X7R2A102K080AA" 0603L 2797.51,686.94 r90 top
C22 "CGA3E2X7R2A103K080AA" 0603L 2856.26,686.94 r90 top
C23 "CGA3E3X7S2A104K080AB" 0603L 2915.01,686.94 r90 top
C24 "CL31B105KCHNNNE" 1206_180 3038.46,639.14 r0 top
D1 "AVDD" LTST-C170KGKT_Green 2607.5,1152.5 r0 top
D2 "nFAULT" LED_LTST-C170_Red 2607.5,1375 r0 top
D3 "ALARM" LED_LTST-C170_Red 2427.5,1462.5 r0 top
D4 "LTST-C170KGKT" LTST-C170KGKT_Green 2675,682.5 r90 top
D5 "BAT165E6327HTSA1" SOD-323 1142.5,425 r180 top
D6 "LTST-C190KRKT" LED_LTST-C190_Red 1209.64,1302.7 r180 top
D7 "LTST-C190GKT" LED_LTST-C190 1209.64,1155.59 r180 top
D8 "CDSU101A" SOD-523F 3599.64,597.8 r180 top
FID1 "Fiducial" Fiducial10-20 420,2457.5 r0 top
FID2 "Fiducial" Fiducial10-20 3879.4,2385 r0 top
FID3 "Fiducial" Fiducial10-20 4125,462.5 r0 top
H1 "NY PMS 440 0025 PH" "NY PMS 440 0025 PH" 217.5,2632.5 r0 top
H2 "NY PMS 440 0025 PH" "NY PMS 440 0025 PH" 4032.5,2632.5 r0 top
H3 "NY PMS 440 0025 PH" "NY PMS 440 0025 PH" 217.5,217.5 r0 top
H4 "NY PMS 440 0025 PH" "NY PMS 440 0025 PH" 4032.5,218.36 r0 top
H5 "Nut" Keystone_1902C 217.5,2632.5 r180 bottom
H6 "Nut" Keystone_1902C 4032.5,2632.5 r180 bottom
H7 "Nut" Keystone_1902C 217.5,217.5 r180 bottom
H8 "Nut" Keystone_1902C 4032.5,218.36 r180 bottom
J1 "SPEED_CTRL_SEL" TSW-103-07-G-D 562.5,2002.5 r180 top
J2 "1051640001" Molex_1051640001 30.41,680.59 r270 top
J3 "Header_3x1" PBC03SAAN 687.5,125 r180 top
J4 "TSW-104-07-G-S" TSW-104-07-G-S 138.36,1160.18 r90 top
J5 "Header_3x1" PBC03SAAN 1500,125 r180 top
J6 "TSW-116-07-G-D" TSW-116-07-G-D 1800,1500 r90 top
J7 "MOTOR_OUT" On-Shore_ED120_3DS 3449.83,336.64 r0 top
J8 "MOTOR_OUT" On-Shore_ED120_3DS 3962.5,1775 r90 top
JP1 "VIN_AVDD_SEL" FP-MTLW-102-07-G-S-230_HDR2-MFG 2925,1407.5 r0 top
L3 "BLM18SG121TZ1D" 0603L 289.64,595.24 r180 top
L4 "SRP1038A-1R0M" SRP1038A 2853.46,359.14 r180 top
LBL1 "THT-14-423-10" Label_650x200 3732.5,1083.2 r180 top
Logo1 "CE Mark" CE_Mark_5mm 1287.85,965 r180 top
Logo2 "Texas Instruments" TI_Stacked_Overlay_Small 870,1690 r0 top
Logo3 "FCC disclaimer" FCC_disclaimer 8817.5,5262.5 r90 top
Logo4 "WEEE logo" WEEE_Minimum 769.14,992.5 r180 top
LOGO5 "CAUTION HOT SURFACE" IEC_HotSurface_Small 3159.37,2010.26 r0 top
LOGO6 "CAUTION HOT SURFACE" IEC_HotSurface_Small 2768.31,1733.62 r180 bottom
NT2 "Net-Tie" Net-Tie_50milWide_30milLong 2287.5,832.5 r270 bottom net-tie
Q1 "FMMT620TA" SOT-23L 3473.46,656.64 r90 top
Q2 "BUK9D23-40EX" FP-BUK9D23-40EX_SOT1220-MFG 3478.46,806.64 r0 top
R1 "RNCF0603TKY10K0" 0603 893,2430.7 r0 top
R2 "RNCF0603TKY10K0" 0603 1488,2431.7 r0 top
R4 "3352T-1-253LF" Bourns_3352T 115,1912.5 r90 top
R5 "ERJ-3GEY0R00V" 0603L 287.5,1912.5 r180 top
R6 "RNCF0603TKY10K0" 0603 637.94,2430.7 r0 top
R7 "RNCF0603TKY10K0" 0603 1232.88,2431.7 r0 top
R9 "RT0603BRD0747RL" 0603 347.5,1787.5 r180 top
R10 "RCG060310K0FKEA" 0603 2862.03,2132.5 r0 top
R13 "RT0603DRE071K74L" 0603 2292.5,2000 r0 top
R14 "RT0603DRE071K74L" 0603 2292.5,1820 r0 top
R15 "ERJ-3GEY0R00V" 0603L 2292.5,1942.5 r0 top
R16 "ERJ-3GEY0R00V" 0603L 2292.5,1885 r0 top
R17 "RC0603FR-071KL" 0603 2677.5,1062.5 r180 top
R18 "RC0603FR-071KL" 0603 2607.5,1450 r0 top
R19 "ERJ-3GEYJ222V" 0603 2428.98,1382.5 r0 top
R20 "RT0603BRD074K7L" 0603L 2702.56,800 r180 top
R21 "ERJ-3GEY0R00V" 0603L 2790.1,2256 r90 top
R22 "ERJ-3GEY0R00V" 0603L 2730.8,2256 r90 top
R23 "ERJ-3GEY0R00V" 0603L 2671.5,2256 r90 top
R24 "ERJ-3GEY0R00V" 0603L 2612.2,2256 r90 top
R27 "ERJ-3GEY0R00V" 0603L 2375,2256 r90 top
R28 "ERJ-3GEY0R00V" 0603L 2493.6,2256 r90 top
R29 "ERJ-3GEY0R00V" 0603L 2434.3,2256 r90 top
R30 "ERJ-3GEY0R00V" 0603L 2552.9,2256 r90 top
R31 "RC0603JR-0747KL" 0603L 232.5,1637.5 r0 top
R32 "RC0603JR-07470RL" 0603L 1209.64,1370.2 r180 top
R33 "RC0603JR-07470RL" 0603L 1209.64,1231.43 r180 top
R34 "CRCW060310K0JNEA" 0603L 3340.96,706.64 r0 top
R35 "CRCW060310K0JNEA" 0603L 3340.96,614.14 r180 top
R36 "RCA12060000ZSEA" 1206L 3162.5,2605 r0 bottom
S1 "SW_SPDT_COM2_1_3" SW_B12AP 765.44,2655.07 r90 top
S2 "SW_SPDT_COM2_1_3" SW_B12AP 1360.44,2656.07 r90 top
S4 "SW_SPST-single" SW_434121025816 203,1505.27 r180 top
SH-J1 "SNT-100-BK-G" SNT-100-BK-G 561.05,2005 r90 top
SH-J2 "SNT-100-BK-G" SNT-100-BK-G 637.5,125 r0 top
SH-J3 "SNT-100-BK-G" SNT-100-BK-G 1450,125 r0 top
SH-J4 "SNT-100-BK-G" SNT-100-BK-G 1800,2250 r180 top
SH-J5 "SNT-100-BK-G" SNT-100-BK-G 1800,2150 r180 top
SH-J6 "SNT-100-BK-G" SNT-100-BK-G 1800,2050 r180 top
SH-J7 "SNT-100-BK-G" SNT-100-BK-G 1800,1950 r180 top
SH-J8 "SNT-100-BK-G" SNT-100-BK-G 1800,1850 r180 top
SH-J9 "SNT-100-BK-G" SNT-100-BK-G 1800,1750 r180 top
SH-J10 "SNT-100-BK-G" SNT-100-BK-G 1800,1650 r180 top
SH-J11 "SNT-100-BK-G" SNT-100-BK-G 1800,1550 r180 top
SH-J12 "SNT-100-BK-G" SNT-100-BK-G 1800,1450 r180 top
SH-J13 "SNT-100-BK-G" SNT-100-BK-G 1800,1350 r180 top
SH-J14 "SNT-100-BK-G" SNT-100-BK-G 1800,1250 r180 top
SH-J15 "SNT-100-BK-G" SNT-100-BK-G 1800,1150 r180 top
SH-J16 "SNT-100-BK-G" SNT-100-BK-G 1800,1050 r180 top
SH-J17 "SNT-100-BK-G" SNT-100-BK-G 1800,950 r0 top
SH-J18 "SNT-100-BK-G" SNT-100-BK-G 1800,850 r0 top
SH-J19 "SNT-100-BK-G" SNT-100-BK-G 1800,750 r0 top
SH-J21 "SNT-100-BK-G" SNT-100-BK-G 2930.07,1400 r180 top
TP1 "EXT_SPEED" Keystone5002 956.95,2192.5 r90 top
TP2 "BRAKE_SW" Keystone5002 765.44,2365.7 r270 top
TP3 "DIR_SW" Keystone5002 1360.44,2366.7 r270 top
TP5 "OUTA" Keystone5000 3585,1575 r90 top
TP6 "OUTB" Keystone5000 3585,1775.39 r90 top
TP7 "EXT_WD" Keystone5002 3330,2372.5 r90 top
TP8 "EXT_CLK" Keystone5002 3335,2572.5 r90 top
TP9 "OUTC" Keystone5000 3585,1975 r90 top
TP10 "VIN_AVDD" Keystone5005 2878.76,1195 r0 top
TP11 "AVDD" Keystone5000 2044.33,2367.5 r90 top
TP12 "DVDD" Keystone5000 2442.5,1667.5 r90 top
TP13 "CP" Keystone5000 3092.5,1197.5 r90 top
TP14 "SPEED/WAKE" Keystone5002 3330,2200 r90 top
TP15 "DACOUT1" Keystone5002 2362.5,1022.5 r90 top
TP16 "DACOUT2" Keystone5002 2547.5,1025 r90 top
TP17 "DACOUT2/SOX" Keystone5002 2252.5,1550 r90 top
TP18 "3V3COM" Keystone5000 1000,525 r90 top
TP19 "5V_USB" Keystone5000 350,820 r90 top
TP20 "5V_EXT" Keystone5000 1000,125 r90 top
TP21 "3V3EXT" Keystone5000 1175,125 r90 top
TP22 "3V3_MCU" Keystone5000 1175,525 r90 top
TP23 "VBAT" Keystone5005 3688.46,739.3 r180 top
TP24 "VM" Keystone5005 2485,539.22 r180 top
TP25 "PGND" Keystone5001 3022.5,795 r270 top
TP26 "AGND" Harwin_D3082-05 1525,550 r180 top
TP27 "AGND" Harwin_D3082-05 2670,2745 r180 top
TP28 "PGND" Harwin_D3082-05 3425,2750 r180 top
TP29 "PGND" Harwin_D3082-05 4150,850 r90 top
TP30 "AGND" Keystone5001 2360,769.18 r90 top
TP31 "AGND" Keystone5001 1156.95,2192.5 r90 top
TP32 "AGND" Keystone5001 125,2250 r90 top
TP33 "AGND" Keystone5001 2322.5,2745 r90 top
TP34 "PGND" Keystone5001 4125,2275 r90 top
TP35 "FG" Keystone5002 2157.5,767.5 r90 top
U1 "MCT8317A0IREER" REE0036A-MFG 2886.63,1850.2 r90 top
U2 "FT232RL" SSOP28_N 696.98,705.42 r270 top
U3 "TPD4E004DRYR" DRY0006A 440,569.59 r180 top
U4 "MSP430FR2355TPTR" PT0048A-MFG 859.64,1253.09 r0 top
Y2 "CSTCR4M00G55B-R0" Murata_CSTCR_G 556.22,1154.67 r270 top
ZZ1 "This Assembly Note is for PCB labels only" AssemblyNoteLabel 80,3460.5 r0 top
ZZ2 "These assemblies are ESD sensitive, ESD precautions shall be observed." AssemblyNote 80,3351.61 r0 top
ZZ3 "These assemblies must be clean and free from flux and all contaminants. Use of no clean flux is not acceptable." AssemblyNote 80,3263.06 r0 top
ZZ4 "These assemblies must comply with workmanship standards IPC-A-610 Class 2, unless otherwise specified." AssemblyNote 80,3174.5 r0 top

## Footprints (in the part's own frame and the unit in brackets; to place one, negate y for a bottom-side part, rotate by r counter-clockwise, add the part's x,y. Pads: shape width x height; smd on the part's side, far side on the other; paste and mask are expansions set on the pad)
0402 [mm] "0402 from SM-752 data"
  rect 0.8x0.6 smd: 1(-0.6,0) 2(0.6,0)
  silkscreen extent -1.22,-0.52 1.22,0.52
0603 [mm] "0603 from SM-752 data"
  rect 1x0.95 smd: 1(-0.8,0) 2(0.8,0)
  silkscreen extent -1.52,-0.69 1.52,0.69
0603L [mm] "0603 from SM-752 data"
  rect 0.8x0.85 smd: 1(-0.7,0) 2(0.7,0)
  silkscreen extent -0.07,-0.33 0.07,0.33
0805L [mm] "0805 from SM-752 data"
  rect 1.1x1.4 smd: 1(-0.75,0) 2(0.75,0)
1206_180 [mm] "1206_180"
  rect 1.1x1.6 smd: 1(-1.7,0) 2(1.7,0)
  silkscreen extent -0.9,-1 0.9,1
1206L [mm] "1206 from SM-752 data"
  rect 1.1x1.75 smd: 1(-1.35,0) 2(1.35,0)
  silkscreen extent -0.4,-0.77 0.4,0.77
1210_270 [mm] "1210"
  rect 1.3x2.7 smd: 1(-1.45,0) 2(1.45,0)
  silkscreen extent -2.32,-1.57 2.32,1.57
AssemblyNote [mil] "Assembly Note"
AssemblyNoteLabel [mil] "Assembly Note for PCB Labels"
Bourns_3352T [mm] "TH, 3-Leads, Body 9.53x8.89mm, Pitch 2.54mm"
  rect 1.35x1.35 hole 0.85: 1(-2.54,0)
  round 1.35 hole 0.85: 2(0,0) 3(2.54,0)
  silkscreen extent -4.44,-2.6 4.44,7.31
CE_Mark_5mm [mil] "Minimum text height for CE Mark"
Chemi-Con_1250x2000 [mm] "TH, 2-Leads, Dia 12.5mm, Lead Sapcing 5mm"
  rect 1.35x1.35 hole 0.85: 1(-2.5,0)
  round 1.35 hole 0.85: 2(2.5,0)
  silkscreen extent -6.5,-6.5 6.5,6.5
DRY0006A [mm] "USON-6"
  rrect67% 0.45x0.3 smd paste-0.05 mask+0: 1(-0.275,0.5)
  rrect67% 0.4x0.3 smd paste-0.05 mask+0: 2(-0.3,0) 3(-0.3,-0.5) 4(0.3,-0.5) 5(0.3,0) 6(0.3,0.5)
FCC_disclaimer [mil]
Fiducial10-20 [mm]
  round 1 smd mask+0: 1(0,0)
  Top Layer keep-out circle w1.178: c0,0 r0.5
FP-BUK9D23-40EX_SOT1220-MFG [mm]
  rrect29% 0.43x0.35 smd paste-1000 mask+0: 1(-0.935,0.65) 2(-0.935,0) 3(-0.935,-0.65) 4(0.935,-0.65) 5(0.935,0) 6(0.935,0.65)
  rrect9% 1.1x1.25 smd paste-1000 mask+0: 7(0,0.285)
  rrect29% 0.66x0.35 smd paste-1000 mask+0: 8(0,-0.775)
  silkscreen extent -1.77,-1.35 1.05,1.35
FP-MTLW-102-07-G-S-230_HDR2-MFG [mm]
  rrect7% 1.52x1.52 hole 1.02 paste-1000 mask+0: 1(-1.27,0)
  round 1.52 hole 1.02 paste-1000 mask+0: 2(1.27,0)
  silkscreen extent -3.27,-1.31 2.67,1.31
Harwin_D3082-05 [mm] "Shorting Plug, 10.16mm spacing, TH"
  round 1.8 hole 1.3: 1(-5.08,0) 2(5.08,0)
  silkscreen extent -3.9,-0.53 3.9,0.53
IEC_HotSurface_Small [mil]
  silkscreen extent -107,-93 107,92
Keystone5000 [mil] "For Keystone 500x miniature loop terminals"
  round 80 hole 40: 1(0,0)
  silkscreen extent -52,-52 52,52
Keystone5001 [mil] "For Keystone 500x miniature loop terminals"
  round 80 hole 40: 1(0,0)
  silkscreen extent -52,-52 52,52
Keystone5002 [mil] "For Keystone 500x miniature loop terminals"
  round 80 hole 40: 1(0,0)
  silkscreen extent -52,-52 52,52
Keystone5005 [mil] "Keystone Compact loops"
  round 87 hole 63: 1(0,0)
  silkscreen extent -70,-70 70,70
Keystone_1902C [mil] "Hex Standoff, 4-40 threaded, nylon"
  round 1 on Mech4: 0(0,0)
Label_650x200 [mil] "Thermal Transfer Label"
  round 1 on Mech13: 0(0,0)
  silkscreen extent -325,-100 325,100
LED_LTST-C170_Red [mm] "LITE-ON"
  rect 1.2x1.2 smd: 1(-1.05,0) 2(1.05,0)
  silkscreen extent -1.6,-1 2.2,1
LED_LTST-C190 [mm] "Lite-On"
  rect 0.8x0.8 smd: 1(-0.75,0) 2(0.75,0)
  silkscreen extent -1.1,-0.8 1.8,0.8
LED_LTST-C190_Red [mm] "Lite-On"
  rect 0.8x0.8 smd: 1(-0.75,0) 2(0.75,0)
  silkscreen extent -1.1,-0.8 1.8,0.8
LTST-C170KGKT_Green [mm] "LITE-ON"
  rect 1.2x1.2 smd: 1(-1.05,0) 2(1.05,0)
  silkscreen extent -1.6,-1 2.2,1
Molex_1051640001 [mm] "Receptacle, USB 2.0, Micro B, 5 Pos, 0.65mm Pitch, R/A, SMT"
  rrect22% 0.45x1.38 smd: 1(1.3,4.11) 2(0.65,4.11) 3(0,4.11) 4(-0.65,4.11) 5(-1.3,4.11)
  rrect7% 1.475x2.1 smd: 6(-2.462,3.75) 11(2.462,3.75)
  rrect100% 1.4x2.1 hole 0.6 slot 1.3 at 90 deg: 7(-3.95,1.45) 10(3.95,1.45)
  rrect7% 1.375x1.9 smd: 8(-0.937,1.45) 9(0.937,1.45)
  silkscreen extent 1.2,5.1 1.4,5.4
Murata_CSTCR_G [mm] "Murata"
  rect 0.4x2.6 smd: 1(-1.5,0) 2(0,0) 3(1.5,0)
Net-Tie_50milWide_30milLong [mil] "50mil net tie, no solder mask opening, no solder paste"
  rect 30x50 smd paste-20 mask+0: 1(-15,0) 2(15,0)
"NY PMS 440 0025 PH" [mm] "4-40 nylon screw and mounting hole"
  round 8 hole 3.2: 1(0,0)
On-Shore_ED120_3DS [mm] "ONSHORE"
  rrect5% 2x2 hole 1.25: 1(-5.08,0)
  round 2 hole 1.25: 2(0,0) 3(5.08,0)
  silkscreen extent -8.14,-4 7.5,5
PBC03SAAN [mm] "Sullins 100mil, 1x3, 230 mil above insulator"
  rect 1.65x1.65 hole 1.016: 1(-2.54,0)
  round 1.65 hole 1.016: 2(0,0) 3(2.54,0)
  silkscreen extent -3.81,-1.27 3.81,1.27
PT0048A-MFG [mm] "Thin QFP, 48-Leads, Body 7x7mm, Pitch 0.5mm, IPC Medium Density"
  rrect33% 1.4x0.3 smd paste-1000 mask+0: 1(-4.25,2.75) 2(-4.25,2.25) 3(-4.25,1.75) 4(-4.25,1.25) 5(-4.25,0.75) 6(-4.25,0.25) 7(-4.25,-0.25) 8(-4.25,-0.75) 9(-4.25,-1.25) 10(-4.25,-1.75) 11(-4.25,-2.25) 12(-4.25,-2.75) 25(4.25,-2.75) 26(4.25,-2.25) 27(4.25,-1.75) 28(4.25,-1.25) 29(4.25,-0.75) 30(4.25,-0.25) 31(4.25,0.25) 32(4.25,0.75) 33(4.25,1.25) 34(4.25,1.75) 35(4.25,2.25) 36(4.25,2.75)
  rrect33% 0.3x1.4 smd paste-1000 mask+0: 13(-2.75,-4.25) 14(-2.25,-4.25) 15(-1.75,-4.25) 16(-1.25,-4.25) 17(-0.75,-4.25) 18(-0.25,-4.25) 19(0.25,-4.25) 20(0.75,-4.25) 21(1.25,-4.25) 22(1.75,-4.25) 23(2.25,-4.25) 24(2.75,-4.25) 37(2.75,4.25) 38(2.25,4.25) 39(1.75,4.25) 40(1.25,4.25) 41(0.75,4.25) 42(0.25,4.25) 43(-0.25,4.25) 44(-0.75,4.25) 45(-1.25,4.25) 46(-1.75,4.25) 47(-2.25,4.25) 48(-2.75,4.25)
  silkscreen extent -5.65,-3.6 3.6,3.6
REE0036A-MFG [mm]
  rrect50% 0.6x0.2 smd paste+0 mask+0: 1(-1.9,1.8) 2(-1.9,1.4) 3(-1.9,1) 4(-1.9,0.6) 5(-1.9,0.2) 6(-1.9,-0.2) 7(-1.9,-0.6) 8(-1.9,-1) 9(-1.9,-1.4) 10(-1.9,-1.8) 19(1.9,-1.8) 20(1.9,-1.4) 21(1.9,-1) 22(1.9,-0.6) 23(1.9,-0.2) 24(1.9,0.2) 25(1.9,0.6) 26(1.9,1) 27(1.9,1.4) 28(1.9,1.8)
  rrect50% 0.2x0.6 smd paste+0 mask+0: 11(-1.4,-2.4) 12(-1,-2.4) 13(-0.6,-2.4) 14(-0.2,-2.4) 15(0.2,-2.4) 16(0.6,-2.4) 17(1,-2.4) 18(1.4,-2.4) 29(1.4,2.4) 30(1,2.4) 31(0.6,2.4) 32(0.2,2.4) 33(-0.2,2.4) 34(-0.6,2.4) 35(-1,2.4) 36(-1.4,2.4)
  rrect7% 2.7x3.7 smd paste-1000 mask+0: 37(0,0)
  silkscreen extent -2.87,-2.55 2.05,2.55
SNT-100-BK-G [mil] "Samtec STEP model"
  round 1 on Mech3: 0(0,0)
SOD-323 [mm] "NXP recommended land pattern"
  rect 0.6x0.6 smd paste-0.05: 1(-1.1,0) 2(1.1,0)
  silkscreen extent -2.06,-0.86 1.53,0.86
SOD-523F [mm] "COMCHIP"
  rect 0.6x0.8 smd paste-0.05: 1(-0.85,0) 2(0.85,0)
  silkscreen extent -1.92,-0.87 1.1,0.87
SOT-23L [mm] "SOT23, 3-Leads, Body 2.9x1.3mm, Pitch 0.95mm, Lead Span 2.5mm, IPC High Density"
  rrect50% 0.8x0.6 smd: 1(-1.1,0.95) 2(-1.1,-0.95) 3(1.1,0)
  silkscreen extent -1.5,-1.5 0.7,1.5
SRP1038A [mm] "SMD, 2-Leads, Body 11x10mm"
  rect 4.1x3.5 smd: 1(-4.75,0) 2(4.75,0)
  silkscreen extent -5,-5 5,5
SSOP28_N [mm] "SOP, 28-Leads, Body 10.2x5.3mm, Pitch 0.65mm, IPC Medium Density"
  oval 2.1x0.45 smd: 1(-3.45,4.225) 2(-3.45,3.575) 3(-3.45,2.925) 4(-3.45,2.275) 5(-3.45,1.625) 6(-3.45,0.975) 7(-3.45,0.325) 8(-3.45,-0.325) 9(-3.45,-0.975) 10(-3.45,-1.625) 11(-3.45,-2.275) 12(-3.45,-2.925) 13(-3.45,-3.575) 14(-3.45,-4.225) 15(3.45,-4.225) 16(3.45,-3.575) 17(3.45,-2.925) 18(3.45,-2.275) 19(3.45,-1.625) 20(3.45,-0.975) 21(3.45,-0.325) 22(3.45,0.325) 23(3.45,0.975) 24(3.45,1.625) 25(3.45,2.275) 26(3.45,2.925) 27(3.45,3.575) 28(3.45,4.225)
  silkscreen extent -3.57,-5.3 2,5.3
SW_434121025816 [mm] "SMD, 2-Leads, Body 6x3.9mm, Pitch 6.5mm"
  rect 1.5x1.4 smd: 1(-3.25,0) 2(3.25,0)
  silkscreen extent -3,-1.95 3,1.95
SW_B12AP [mm] "NKK Switches"
  rect 1.35x1.35 hole 0.85 paste+0: 1(-1,2.54)
  round 1.35 hole 0.85 paste+0: 2(-1,0) 3(-1,-2.54)
  silkscreen extent -4.27,-4.4 3.4,4.4
TI_Stacked_Overlay_Small [mil]
TSW-103-07-G-D [mm] "Samtec 100mil, 2x3, 230 mil above insulator"
  rect 1.65x1.65 hole 1.016: 1(-2.54,-1.27)
  round 1.65 hole 1.016: 2(-2.54,1.27) 3(0,-1.27) 4(0,1.27) 5(2.54,-1.27) 6(2.54,1.27)
  silkscreen extent -4.84,-2.54 3.81,2.54
TSW-104-07-G-S [mm] "Samtec 100mil, 1x4, 230 mil above insulator"
  rrect50% 1.65x1.65 hole 1.016: 1(-3.81,0)
  round 1.65 hole 1.016: 2(-1.27,0) 3(1.27,0) 4(3.81,0)
TSW-116-07-G-D [mm] "Samtec 100mil, 2x16, 230 mil above insulator"
  rrect6% 1.65x1.65 hole 1.016: 1(-19.05,-1.27)
  round 1.65 hole 1.016: 2(-19.05,1.27) 3(-16.51,-1.27) 4(-16.51,1.27) 5(-13.97,-1.27) 6(-13.97,1.27) 7(-11.43,-1.27) 8(-11.43,1.27) 9(-8.89,-1.27) 10(-8.89,1.27) 11(-6.35,-1.27) 12(-6.35,1.27) 13(-3.81,-1.27) 14(-3.81,1.27) 15(-1.27,-1.27) 16(-1.27,1.27) 17(1.27,-1.27) 18(1.27,1.27) 19(3.81,-1.27) 20(3.81,1.27) 21(6.35,-1.27) 22(6.35,1.27) 23(8.89,-1.27) 24(8.89,1.27) 25(11.43,-1.27) 26(11.43,1.27) 27(13.97,-1.27) 28(13.97,1.27) 29(16.51,-1.27) 30(16.51,1.27) 31(19.05,-1.27) 32(19.05,1.27)
  silkscreen extent -21.34,-2.54 20.32,2.54
WEEE_Minimum [mil] "WEEElie bin"

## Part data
C1: library part CMP-0080104-1, "CAP, CERM, 1 µF, 16 V,+/- 10%, X7R, AEC-Q200 Grade 1, 0603"
C2: library part CMP-0006812-1, "CAP, CERM, 100 pF, 10 V, +/- 10%, X7R, 0603"
C3 C5: library part CMP-0086190-1, "CAP, CERM, 1 µF, 6.3 V,+/- 10%, X7R, AEC-Q200 Grade 1, 0603"
C4 C7: library part CMP-0006289-1, "CAP, CERM, 0.1 uF, 50 V, +/- 10%, X6S, 0402"
C6: library part CMP-0009229-1, "CAP, CERM, 10 uF, 63 V, +/- 10%, X7R, 1210"
C10 C11 C13: library part CMP-0006815-4, "CAP, CERM, 0.1 uF, 10 V, +/- 10%, X7R, 0603"
C12: library part CMP-0007498-4, "CAP, CERM, 4.7 uF, 10 V, +/- 20%, X7R, 0603"
C14: library part CMP-0006826-4, "CAP, CERM, 1000 pF, 16 V, +/- 10%, X7R, 0603"
C15: library part CMP-0007696-2, "CAP, CERM, 1 uF, 50 V, +/- 10%, X7R, 0805"
C16: library part CMP-0009912-2, "CAP, AL, 330 uF, 63 V, +/- 20%, AEC-Q200 Grade 2, TH"
C17 C24: library part CMP-0008801-2, "CAP, CERM, 1 uF, 100 V, +/- 10%, X7R, 1206"
C18 C23: library part CMP-0007099-4, "CAP, CERM, 0.1 uF, 100 V, +/- 10%, X7S, AEC-Q200 Grade 1, 0603"
C19 C22: library part CMP-0007082-4, "CAP, CERM, 0.01 uF, 100 V, +/- 10%, X7R, AEC-Q200 Grade 1, 0603"
C20 C21: library part CMP-0007081-4, "CAP, CERM, 1000 pF, 100 V, +/- 10%, X7R, AEC-Q200 Grade 1, 0603"
D1 D4: library part CMP-0002888-2, "LED, Green, SMD"
D2 D3: library part CMP-0002829-3, "LED, Red, SMD"
D5: library part CMP-0028882-2, "Diode, Schottky, 40 V, 0.75 A, AEC-Q101, SOD-323"
D6: library part CMP-0078131-2, "LED, Red, SMD"
D7: library part CMP-0002827-2, "LED, Green, SMD"
D8: library part CMP-0076943-3, "Diode, Switching, 90 V, 0.1 A, SOD-523F"
FID1 FID2 FID3: library part CMP-0077181-1, "Fiducial mark.  There is nothing to buy or mount."
H1 H2 H3 H4: library part CMP-0003617-1, "Machine Screw, Round, #4-40 x 1/4, Nylon, Philips panhead"
H5 H6 H7 H8: library part CMP-0003610-1, "Standoff, Hex, 0.5\"L #4-40 Nylon"
J1: library part CMP-0075406-2, "Header, 100mil, 3x2, Gold, TH"
J2: library part CMP-0055311-1, "Receptacle, USB 2.0, Micro B, 5 Position, R/A, SMT"
J3 J5: library part CMP-0002334-1, "Header, 100mil, 3x1, Gold, TH"
J4: library part CMP-0075409-2, "Header, 100mil, 4x1, Gold, TH"
J6: library part CMP-0075429-1, "Header, 100mil, 16x2, Gold, TH"
J7 J8: library part CMP-0074911-1, "Terminal Block, 5.08 mm, 3x1, Brass, TH"
JP1: library part CMP-0090697-1, "Conn Unshrouded Header HDR 2 POS 2.54mm Solder ST Thru-Hole"
L3: library part CMP-0084877-1, "Inductor, Ferrite Bead, Ferrite, 3 A, 120 ohm, AEC-Q200 Grade 1, SMD"
L4: library part CMP-0056795-1, "Inductor, Shielded, Powdered Iron, 1 uH, 18 A, 0.003 ohm, AEC-Q200 Grade 1, SMD"
LBL1: library part CMP-0003625-1
Logo1: library part CMP-0074844-1
Logo2: library part CMP-0074838-1, "Texas Instrument Corporate Signature"
Logo3: library part CMP-0074847-1, "FCC_disclaimer"
Logo4: library part CMP-0074769-1
LOGO5 LOGO6: library part CMP-0074837-1, "IEC 61010-1 Hot Surface Warning"
NT2: library part CMP-0078142-4, "Single point connection between nets."
Q1: library part CMP-0000467-2, "Transistor, NPN, 80 V, 1.5 A, AEC-Q101, SOT-23"
Q2: library part CMP-0088880-1, "N-Channel 40V 8A (Ta) 15W (Tc) Surface Mount DFN2020MD-6"
R1 R2 R6 R7: library part CMP-0023626-2, "RES, 10.0 k, 0.01%, 0.063 W, 0603"
R4: library part CMP-0001776-2, "Trimmer Potentiometer, 25kohm, 0.5W, TH"
R5 R15 R16 R21 R22 R23 R24 R27 R28 R29 R30: library part CMP-0025874-4, "RES, 0, 5%, 0.1 W, AEC-Q200 Grade 0, 0603"
R9: library part CMP-0024269-1, "RES, 47.0, 0.1%, 0.1 W, 0603"
R10: library part CMP-0023337-3, "RES, 10.0 k, 1%, 0.1 W, 0603"
R13 R14: library part CMP-0024840-3, "RES, 1.74 k, 0.5%, 0.1 W, 0603"
R17 R18: library part CMP-0022895-5, "RES, 1.00 k, 1%, 0.1 W, 0603"
R19: library part CMP-0025879-1, "RES, 2.2 k, 5%, 0.1 W, AEC-Q200 Grade 0, 0603"
R20: library part CMP-0024300-2, "RES, 4.70 k, 0.1%, 0.1 W, 0603"
R31: library part CMP-0025925-5, "RES, 47 k, 5%, 0.1 W, 0603"
R32 R33: library part CMP-0025924-5, "RES, 470, 5%, 0.1 W, 0603"
R34 R35: library part CMP-0025701-4, "RES, 10 k, 5%, 0.1 W, AEC-Q200 Grade 0, 0603"
R36: library part CMP-0018760-2, "RES, 0, 5%, 0.25 W, AEC-Q200 Grade 0, 1206"
S1 S2: library part CMP-0002155-2, "SWITCH TOGGLE SPDT 0.4VA 28V"
S4: library part CMP-0002196-2, "Switch, Tactile, SPST, 12 V, SMD"
SH-J1 SH-J2 SH-J3 SH-J4 SH-J5 SH-J6 SH-J7 SH-J8 SH-J9 SH-J10 SH-J11 SH-J12 SH-J13 SH-J14 SH-J15 SH-J16 SH-J17 SH-J18 SH-J19 SH-J21: library part CMP-0003623-3, "Shunt, 100mil, Gold plated, Black"
TP1 TP2 TP3 TP7 TP8 TP14 TP15 TP16 TP17 TP35: library part CMP-0055139-1, "Test Point, Miniature, White, TH"
TP5 TP6 TP9 TP11 TP12 TP13 TP18 TP19 TP20 TP21 TP22: library part CMP-0055137-1, "Test Point, Miniature, Red, TH"
TP10 TP23 TP24: library part CMP-0055142-1, "Test Point, Compact, Red, TH"
TP25 TP30 TP31 TP32 TP33 TP34: library part CMP-0055138-1, "Test Point, Miniature, Black, TH"
TP26 TP27 TP28 TP29: library part CMP-0075110-1, "1mm Uninsulated Shorting Plug, 10.16mm spacing, TH"
U1: library part CMP-0096865-1, "High Speed Sensorless Trapezoidal Control Integrated FET BLDC Driver"
U2: library part CMP-0004774-1, "USB to Serial UART, SSOP28"
U3: library part CMP-0043115-3, "4-Channel ESD Protection Array for High-Speed Data Interfaces, DRY0006A (USON-6)"
U4: library part CMP-0089204-1, "CPU16 MSP430™ FRAM Microcontroller IC 16-Bit 24MHz 32KB (32K x 8) FRAM 48-LQFP (7x7)"
Y2: library part CMP-0084387-1, "Resonator, 4 MHz, 39 pF, AEC-Q200 Grade 1, SMD"
ZZ1: library part CMP-0003616-3
ZZ2: library part CMP-0077236-1
ZZ3: library part CMP-0077237-1
ZZ4: library part CMP-0077238-1

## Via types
v1: diameter 20, hole 10, Top Layer to Bottom Layer, tented both sides, 600 vias
v2: diameter 25, hole 10, Top Layer to Bottom Layer, tented both sides, 30 vias
v3: diameter 19.68, hole 7.87, Top Layer to Bottom Layer, tented both sides, 8 vias
v4: diameter 25, hole 10, Top Layer to Bottom Layer, 1 vias

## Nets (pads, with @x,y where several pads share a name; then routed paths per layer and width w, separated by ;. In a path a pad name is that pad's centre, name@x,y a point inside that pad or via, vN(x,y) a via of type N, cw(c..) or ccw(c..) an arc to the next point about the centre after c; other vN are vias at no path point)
3V3_MCU: C15.1 D5.1 J4.2 J5.2 R31.2 R32.2 R33.2 TP22.1 U4.6 | length 434.2
  Top Layer w10: R31.2@260.06,1637.5 v1(297.5,1637.5) ; 627.54,1275.51 640.11,1262.93 693.3,1262.93 v1(752.5,1262.93) ; v1(1131.95,1214.99) 1148.39,1231.43 R33.2@1182.08,1231.43 ; v1(1137.5,1370) 1181.88,1370 R32.2@1182.08,1370.2
  Top Layer w20: C15.1@572.03,1287.5 615.54,1287.5 627.54,1275.51 ; TP22.1@1175,525 1185.81,514.19 D5.1@1185.81,425
3V3COM: C11.1 D5.2 J5.3 TP18.1 U2.4 U2.17 | length 1382.9
  Top Layer w15: U2.17@581.82,569.59 581.82,635.04 644.88,698.09 746.19,698.09 786.55,738.45 U2.4@786.55,841.24 786.55,894.06 C11.1@819.58,927.09
  Top Layer w20: 786.55,738.45 TP18.1@1000,525 J5.3@1400,125
3V3EXT: J5.1 TP21.1 | length 485.1
  Top Layer w20: TP21.1@1175,125 1247.5,52.5 1527.5,52.5 J5.1@1600,125
5V_EXT: J3.1 TP20.1 | length 212.5
  Top Layer w20: J3.1@787.5,125 TP20.1@1000,125
5V_USB: C10.1 J3.3 L3.1 TP19.1 U3.6 | length 510.5
  Top Layer w10: v1(407.5,542.5) 414.91,549.91 U3.6@428.19,549.91
  Top Layer w30: 355.49,515.64 587.5,283.63 J3.3@587.5,125
  other v1: 349.64,538.74 349.78,565.08 349.64,594.33
5VCC: C12.2 C13.1 J3.2 U2.20 | length 440.1
  Top Layer w10: 658.6,461.54 U2.20@658.6,569.59
  Top Layer w25: J3.2@687.5,125 687.73,125.23 C13.1@687.73,456.96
